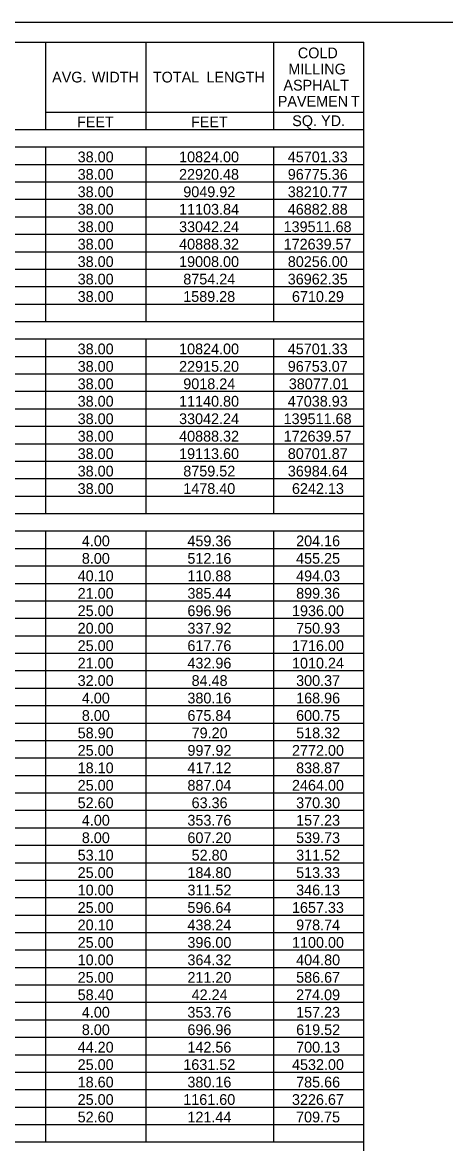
# Model space of a CAD drawing. Extents: x 2261867 to 2275370, y -3124789 to -3122260.
# Drawn here: x 2267667 to 2267860, y -3124304 to -3123790 of the extents above; entities that cross this region are included whole.
import ezdxf

# ---------------------------------------------------------------- set-up
doc = ezdxf.new("R2010")
doc.units = 0
doc.layers.add('Default', color=7, linetype='Continuous')
doc.layers.add('DSN_DRFT_Named-Boundary', color=7, linetype='Continuous')

msp = doc.modelspace()

# ---------------------------------------------------------------- linework, layer by layer
at = {"layer": 'Default'}
for p, q in [((2267341.29, -3123799.38), (2267822.99, -3123799.38)), ((2267677.48, -3123839.36), (2267677.48, -3123799.38)), ((2267723.45, -3123839.36), (2267723.45, -3123799.38)), ((2267781.81, -3123839.36), (2267781.81, -3123799.38)), ((2267822.99, -3124734.8), (2267822.99, -3123799.38)), ((2267822.99, -3124734.8), (2267822.99, -3123799.38)), ((2267677.48, -3123831.36), (2267822.99, -3123831.36)), ((2267677.48, -3123839.36), (2267677.48, -3123831.36)), ((2267723.45, -3123839.36), (2267723.45, -3123831.36)), ((2267341.29, -3123839.36), (2267822.99, -3123839.36)), ((2267341.29, -3123847.35), (2267822.99, -3123847.35)), ((2267341.29, -3123847.35), (2267822.99, -3123847.35)), ((2267677.48, -3123927.3), (2267677.48, -3123847.35)), ((2267677.48, -3123927.3), (2267677.48, -3123847.35)), ((2267723.45, -3123927.3), (2267723.45, -3123847.35)), ((2267781.81, -3123927.3), (2267781.81, -3123847.35)), ((2267341.29, -3123855.35), (2267822.99, -3123855.35)), ((2267723.45, -3123855.35), (2267822.99, -3123855.35)), ((2267382.46, -3123863.34), (2267723.45, -3123863.34)), ((2267677.48, -3123863.34), (2267723.45, -3123863.34)), ((2267723.45, -3123863.34), (2267822.99, -3123863.34)), ((2267723.45, -3123871.34), (2267723.45, -3123863.34)), ((2267382.46, -3123871.34), (2267822.99, -3123871.34)), ((2267677.48, -3123871.34), (2267822.99, -3123871.34)), ((2267382.46, -3123879.33), (2267822.99, -3123879.33)), ((2267677.48, -3123879.33), (2267781.81, -3123879.33)), ((2267781.81, -3123879.33), (2267822.99, -3123879.33)), ((2267382.46, -3123887.33), (2267781.81, -3123887.33)), ((2267677.48, -3123887.33), (2267781.81, -3123887.33)), ((2267781.81, -3123887.33), (2267822.99, -3123887.33)), ((2267781.81, -3123895.32), (2267781.81, -3123887.33)), ((2267341.29, -3123895.32), (2267822.99, -3123895.32)), ((2267723.45, -3123903.32), (2267723.45, -3123895.32)), ((2267781.81, -3123895.32), (2267822.99, -3123895.32)), ((2267382.46, -3123903.32), (2267822.99, -3123903.32)), ((2267677.48, -3123903.32), (2267822.99, -3123903.32)), ((2267382.46, -3123911.31), (2267822.99, -3123911.31)), ((2267677.48, -3123911.31), (2267781.81, -3123911.31)), ((2267781.81, -3123911.31), (2267822.99, -3123911.31)), ((2267382.46, -3123919.31), (2267822.99, -3123919.31)), ((2267677.48, -3123919.31), (2267781.81, -3123919.31)), ((2267781.81, -3123919.31), (2267822.99, -3123919.31)), ((2267341.29, -3123927.3), (2267822.99, -3123927.3)), ((2267423.64, -3123927.3), (2267677.48, -3123927.3)), ((2267677.48, -3123927.3), (2267723.45, -3123927.3)), ((2267723.45, -3123927.3), (2267822.99, -3123927.3)), ((2267341.29, -3123935.3), (2267822.99, -3123935.3)), ((2267677.48, -3124015.25), (2267677.48, -3123935.3)), ((2267677.48, -3124015.25), (2267677.48, -3123935.3)), ((2267723.45, -3124015.25), (2267723.45, -3123935.3)), ((2267723.45, -3123943.29), (2267723.45, -3123935.3)), ((2267781.81, -3124015.25), (2267781.81, -3123935.3)), ((2267781.81, -3123943.29), (2267781.81, -3123935.3)), ((2267341.29, -3123943.29), (2267822.99, -3123943.29)), ((2267723.45, -3123943.29), (2267822.99, -3123943.29)), ((2267341.29, -3123951.29), (2267822.99, -3123951.29)), ((2267723.45, -3123951.29), (2267781.81, -3123951.29)), ((2267781.81, -3123951.29), (2267822.99, -3123951.29)), ((2267382.46, -3123959.28), (2267822.99, -3123959.28)), ((2267677.48, -3123959.28), (2267822.99, -3123959.28)), ((2267723.45, -3123967.28), (2267723.45, -3123959.28)), ((2267382.46, -3123967.28), (2267822.99, -3123967.28)), ((2267677.48, -3123967.28), (2267822.99, -3123967.28)), ((2267382.46, -3123975.27), (2267822.99, -3123975.27)), ((2267677.48, -3123975.27), (2267822.99, -3123975.27)), ((2267382.46, -3123983.27), (2267822.99, -3123983.27)), ((2267677.48, -3123983.27), (2267781.81, -3123983.27)), ((2267781.81, -3123983.27), (2267822.99, -3123983.27)), ((2267382.46, -3123991.26), (2267822.99, -3123991.26)), ((2267677.48, -3123991.26), (2267781.81, -3123991.26)), ((2267781.81, -3123991.26), (2267822.99, -3123991.26)), ((2267382.46, -3123999.26), (2267822.99, -3123999.26)), ((2267677.48, -3123999.26), (2267781.81, -3123999.26)), ((2267781.81, -3123999.26), (2267822.99, -3123999.26)), ((2267382.46, -3124007.25), (2267822.99, -3124007.25)), ((2267677.48, -3124007.25), (2267781.81, -3124007.25)), ((2267781.81, -3124007.25), (2267822.99, -3124007.25)), ((2267341.29, -3124015.25), (2267822.99, -3124015.25)), ((2267423.64, -3124015.25), (2267677.48, -3124015.25)), ((2267677.48, -3124015.25), (2267781.81, -3124015.25)), ((2267781.81, -3124015.25), (2267822.99, -3124015.25)), ((2267341.29, -3124023.24), (2267822.99, -3124023.24)), ((2267677.48, -3124023.24), (2267723.45, -3124023.24)), ((2267677.48, -3124303.07), (2267677.48, -3124023.24)), ((2267677.48, -3124303.07), (2267677.48, -3124023.24)), ((2267723.45, -3124023.24), (2267781.81, -3124023.24)), ((2267723.45, -3124303.07), (2267723.45, -3124023.24)), ((2267723.45, -3124303.07), (2267723.45, -3124023.24)), ((2267781.81, -3124303.07), (2267781.81, -3124023.24)), ((2267781.81, -3124303.07), (2267781.81, -3124023.24)), ((2267341.29, -3124031.24), (2267781.81, -3124031.24)), ((2267723.45, -3124031.24), (2267781.81, -3124031.24)), ((2267781.81, -3124031.24), (2267822.99, -3124031.24)), ((2267341.29, -3124039.23), (2267781.81, -3124039.23)), ((2267723.45, -3124039.23), (2267781.81, -3124039.23)), ((2267781.81, -3124039.23), (2267822.99, -3124039.23)), ((2267341.29, -3124047.23), (2267781.81, -3124047.23)), ((2267723.45, -3124047.23), (2267781.81, -3124047.23)), ((2267781.81, -3124047.23), (2267822.99, -3124047.23)), ((2267341.29, -3124055.22), (2267781.81, -3124055.22)), ((2267723.45, -3124055.22), (2267781.81, -3124055.22)), ((2267781.81, -3124055.22), (2267822.99, -3124055.22)), ((2267341.29, -3124063.22), (2267781.81, -3124063.22)), ((2267723.45, -3124063.22), (2267781.81, -3124063.22)), ((2267781.81, -3124063.22), (2267822.99, -3124063.22)), ((2267341.29, -3124071.21), (2267781.81, -3124071.21)), ((2267723.45, -3124071.21), (2267781.81, -3124071.21)), ((2267781.81, -3124071.21), (2267822.99, -3124071.21)), ((2267341.29, -3124079.21), (2267781.81, -3124079.21)), ((2267723.45, -3124079.21), (2267781.81, -3124079.21)), ((2267781.81, -3124079.21), (2267822.99, -3124079.21)), ((2267341.29, -3124087.2), (2267781.81, -3124087.2)), ((2267723.45, -3124087.2), (2267781.81, -3124087.2)), ((2267781.81, -3124087.2), (2267822.99, -3124087.2)), ((2267341.29, -3124095.2), (2267781.81, -3124095.2)), ((2267723.45, -3124095.2), (2267781.81, -3124095.2)), ((2267781.81, -3124095.2), (2267822.99, -3124095.2)), ((2267341.29, -3124103.19), (2267781.81, -3124103.19)), ((2267723.45, -3124103.19), (2267781.81, -3124103.19)), ((2267781.81, -3124103.19), (2267822.99, -3124103.19)), ((2267341.29, -3124111.19), (2267781.81, -3124111.19)), ((2267723.45, -3124111.19), (2267781.81, -3124111.19)), ((2267781.81, -3124111.19), (2267822.99, -3124111.19)), ((2267341.29, -3124119.18), (2267781.81, -3124119.18)), ((2267723.45, -3124119.18), (2267781.81, -3124119.18)), ((2267781.81, -3124119.18), (2267822.99, -3124119.18)), ((2267341.29, -3124127.18), (2267781.81, -3124127.18)), ((2267723.45, -3124127.18), (2267781.81, -3124127.18)), ((2267781.81, -3124127.18), (2267822.99, -3124127.18)), ((2267341.29, -3124135.17), (2267781.81, -3124135.17)), ((2267723.45, -3124135.17), (2267781.81, -3124135.17)), ((2267781.81, -3124135.17), (2267822.99, -3124135.17)), ((2267341.29, -3124143.17), (2267781.81, -3124143.17)), ((2267723.45, -3124143.17), (2267781.81, -3124143.17)), ((2267781.81, -3124143.17), (2267822.99, -3124143.17)), ((2267341.29, -3124151.16), (2267781.81, -3124151.16)), ((2267723.45, -3124151.16), (2267781.81, -3124151.16)), ((2267781.81, -3124151.16), (2267822.99, -3124151.16)), ((2267341.29, -3124159.16), (2267781.81, -3124159.16)), ((2267723.45, -3124159.16), (2267781.81, -3124159.16)), ((2267781.81, -3124159.16), (2267822.99, -3124159.16)), ((2267341.29, -3124167.15), (2267781.81, -3124167.15)), ((2267723.45, -3124167.15), (2267781.81, -3124167.15)), ((2267781.81, -3124167.15), (2267822.99, -3124167.15)), ((2267341.29, -3124175.15), (2267781.81, -3124175.15)), ((2267723.45, -3124175.15), (2267781.81, -3124175.15)), ((2267781.81, -3124175.15), (2267822.99, -3124175.15)), ((2267341.29, -3124183.14), (2267781.81, -3124183.14)), ((2267723.45, -3124183.14), (2267781.81, -3124183.14)), ((2267781.81, -3124183.14), (2267822.99, -3124183.14)), ((2267341.29, -3124191.14), (2267781.81, -3124191.14)), ((2267723.45, -3124191.14), (2267781.81, -3124191.14)), ((2267781.81, -3124191.14), (2267822.99, -3124191.14)), ((2267341.29, -3124199.13), (2267781.81, -3124199.13)), ((2267723.45, -3124199.13), (2267781.81, -3124199.13)), ((2267781.81, -3124199.13), (2267822.99, -3124199.13)), ((2267341.29, -3124207.13), (2267781.81, -3124207.13)), ((2267723.45, -3124207.13), (2267781.81, -3124207.13)), ((2267781.81, -3124207.13), (2267822.99, -3124207.13)), ((2267341.29, -3124215.12), (2267781.81, -3124215.12)), ((2267723.45, -3124215.12), (2267781.81, -3124215.12)), ((2267781.81, -3124215.12), (2267822.99, -3124215.12)), ((2267341.29, -3124223.12), (2267781.81, -3124223.12)), ((2267723.45, -3124223.12), (2267781.81, -3124223.12)), ((2267781.81, -3124223.12), (2267822.99, -3124223.12)), ((2267341.29, -3124231.11), (2267781.81, -3124231.11)), ((2267723.45, -3124231.11), (2267781.81, -3124231.11)), ((2267781.81, -3124231.11), (2267822.99, -3124231.11)), ((2267341.29, -3124239.11), (2267781.81, -3124239.11)), ((2267723.45, -3124239.11), (2267781.81, -3124239.11)), ((2267781.81, -3124239.11), (2267822.99, -3124239.11)), ((2267341.29, -3124247.1), (2267781.81, -3124247.1)), ((2267723.45, -3124247.1), (2267781.81, -3124247.1)), ((2267781.81, -3124247.1), (2267822.99, -3124247.1)), ((2267341.29, -3124255.1), (2267781.81, -3124255.1)), ((2267723.45, -3124255.1), (2267781.81, -3124255.1)), ((2267781.81, -3124255.1), (2267822.99, -3124255.1)), ((2267341.29, -3124263.09), (2267781.81, -3124263.09)), ((2267677.48, -3124263.09), (2267781.81, -3124263.09)), ((2267781.81, -3124263.09), (2267822.99, -3124263.09)), ((2267341.29, -3124271.09), (2267781.81, -3124271.09)), ((2267677.48, -3124271.09), (2267781.81, -3124271.09)), ((2267781.81, -3124271.09), (2267822.99, -3124271.09)), ((2267341.29, -3124279.08), (2267781.81, -3124279.08)), ((2267677.48, -3124279.08), (2267781.81, -3124279.08)), ((2267781.81, -3124279.08), (2267822.99, -3124279.08)), ((2267341.29, -3124287.08), (2267781.81, -3124287.08)), ((2267677.48, -3124287.08), (2267781.81, -3124287.08)), ((2267781.81, -3124287.08), (2267822.99, -3124287.08)), ((2267341.29, -3124295.07), (2267781.81, -3124295.07)), ((2267677.48, -3124295.07), (2267781.81, -3124295.07)), ((2267781.81, -3124295.07), (2267822.99, -3124295.07)), ((2267341.29, -3124303.07), (2267677.48, -3124303.07)), ((2267341.29, -3124303.07), (2267822.99, -3124303.07)), ((2267677.48, -3124303.07), (2267781.81, -3124303.07)), ((2267781.81, -3124303.07), (2267822.99, -3124303.07))]:
    msp.add_line(p, q, dxfattribs=at)
at = {"layer": 'DSN_DRFT_Named-Boundary'}
msp.add_lwpolyline([(2266769.64, -3124789.38), (2268394.64, -3124789.38), (2268394.64, -3123790.32), (2266769.64, -3123790.32)], close=True, dxfattribs=at)

# ---------------------------------------------------------------- texts
at = {"layer": 'Default'}
for s, p in [('COLD', (2267792.83, -3123806.76)), ('AVG.', (2267680.34, -3123817.83)), (' WIDTH', (2267696.68, -3123817.83)), ('TOTAL', (2267726.46, -3123817.83)), (' LENGTH', (2267749.16, -3123817.83)), ('MILLING', (2267788.48, -3123814.14)), ('ASPHALT', (2267786.24, -3123821.52)), ('PAVEMEN', (2267783.65, -3123828.9)), ('T', (2267817.1, -3123828.9)), ('FEET', (2267691.75, -3123838.37)), ('FEET', (2267743.92, -3123838.37)), ('SQ.', (2267790.27, -3123837.82)), (' YD.', (2267801.64, -3123837.82)), ('38.00', (2267692.03, -3123854.36)), ('10824.00', (2267738.47, -3123854.36)), ('45701.33', (2267788.23, -3123854.36)), ('38.00', (2267692.03, -3123862.36)), ('22920.48', (2267738.45, -3123862.36)), ('96775.36', (2267788.23, -3123862.36)), ('38.00', (2267692.03, -3123870.35)), ('9049.92', (2267740.39, -3123870.35)), ('38210.77', (2267788.23, -3123870.35)), ('38.00', (2267692.03, -3123878.35)), ('11103.84', (2267738.47, -3123878.35)), ('46882.88', (2267788.22, -3123878.35)), ('38.00', (2267692.03, -3123886.34)), ('33042.24', (2267738.47, -3123886.34)), ('139511.68', (2267786.31, -3123886.34)), ('38.00', (2267692.03, -3123894.34)), ('40888.32', (2267738.48, -3123894.34)), ('172639.57', (2267786.32, -3123894.34)), ('38.00', (2267692.03, -3123902.33)), ('19008.00', (2267738.47, -3123902.33)), ('80256.00', (2267788.24, -3123902.33)), ('38.00', (2267692.03, -3123910.33)), ('8754.24', (2267740.38, -3123910.33)), ('36962.35', (2267788.21, -3123910.33)), ('38.00', (2267692.03, -3123918.32)), ('1589.28', (2267740.36, -3123918.32)), ('6710.29', (2267790.13, -3123918.32)), ('38.00', (2267692.03, -3123942.31)), ('10824.00', (2267738.47, -3123942.31)), ('45701.33', (2267788.23, -3123942.31)), ('38.00', (2267692.03, -3123950.3)), ('22915.20', (2267738.47, -3123950.3)), ('96753.07', (2267788.23, -3123950.3)), ('38.00', (2267692.03, -3123958.3)), ('9018.24', (2267740.38, -3123958.3)), ('38077.01', (2267788.7, -3123958.3)), ('38.00', (2267692.03, -3123966.29)), ('11140.80', (2267738.47, -3123966.29)), ('47038.93', (2267788.23, -3123966.29)), ('38.00', (2267692.03, -3123974.29)), ('33042.24', (2267738.47, -3123974.29)), ('139511.68', (2267786.31, -3123974.29)), ('38.00', (2267692.03, -3123982.28)), ('40888.32', (2267738.48, -3123982.28)), ('172639.57', (2267786.32, -3123982.28)), ('38.00', (2267692.03, -3123990.28)), ('19113.60', (2267738.47, -3123990.28)), ('80701.87', (2267788.23, -3123990.28)), ('38.00', (2267692.03, -3123998.27)), ('8759.52', (2267740.39, -3123998.27)), ('36984.64', (2267788.24, -3123998.27)), ('38.00', (2267692.03, -3124006.27)), ('1478.40', (2267740.38, -3124006.27)), ('6242.13', (2267790.14, -3124006.27)), ('4.00', (2267693.94, -3124030.25)), ('459.36', (2267742.28, -3124030.25)), ('204.16', (2267792.05, -3124030.25)), ('8.00', (2267693.94, -3124038.25)), ('512.16', (2267742.28, -3124038.25)), ('455.25', (2267792.03, -3124038.25)), ('40.10', (2267692.03, -3124046.24)), ('110.88', (2267742.27, -3124046.24)), ('494.03', (2267792.05, -3124046.24)), ('21.00', (2267692.03, -3124054.24)), ('385.44', (2267742.29, -3124054.24)), ('899.36', (2267792.05, -3124054.24)), ('25.00', (2267692.03, -3124062.23)), ('696.96', (2267742.28, -3124062.23)), ('1936.00', (2267790.15, -3124062.23)), ('20.00', (2267692.03, -3124070.23)), ('337.92', (2267742.3, -3124070.23)), ('750.93', (2267792.05, -3124070.23)), ('25.00', (2267692.03, -3124078.22)), ('617.76', (2267742.28, -3124078.22)), ('1716.00', (2267790.15, -3124078.22)), ('21.00', (2267692.03, -3124086.22)), ('432.96', (2267742.28, -3124086.22)), ('1010.24', (2267790.15, -3124086.22)), ('32.00', (2267692.03, -3124094.21)), ('84.48', (2267744.19, -3124094.21)), ('300.37', (2267792.05, -3124094.21)), ('4.00', (2267693.94, -3124102.21)), ('380.16', (2267742.28, -3124102.21)), ('168.96', (2267792.05, -3124102.21)), ('8.00', (2267693.94, -3124110.2)), ('675.84', (2267742.29, -3124110.2)), ('600.75', (2267792.03, -3124110.2)), ('58.90', (2267692.03, -3124118.2)), ('79.20', (2267744.2, -3124118.2)), ('518.32', (2267792.07, -3124118.2)), ('25.00', (2267692.03, -3124126.19)), ('997.92', (2267742.3, -3124126.19)), ('2772.00', (2267790.15, -3124126.19)), ('18.10', (2267692.03, -3124134.19)), ('417.12', (2267742.3, -3124134.19)), ('838.87', (2267792.05, -3124134.19)), ('25.00', (2267692.03, -3124142.18)), ('887.04', (2267742.29, -3124142.18)), ('2464.00', (2267790.15, -3124142.18)), ('52.60', (2267692.03, -3124150.18)), ('63.36', (2267744.19, -3124150.18)), ('370.30', (2267792.06, -3124150.18)), ('4.00', (2267693.94, -3124158.17)), ('353.76', (2267742.28, -3124158.17)), ('157.23', (2267792.05, -3124158.17)), ('8.00', (2267693.94, -3124166.17)), ('607.20', (2267742.29, -3124166.17)), ('539.73', (2267792.05, -3124166.17)), ('53.10', (2267692.03, -3124174.16)), ('52.80', (2267744.2, -3124174.16)), ('311.52', (2267792.07, -3124174.16)), ('25.00', (2267692.03, -3124182.16)), ('184.80', (2267742.29, -3124182.16)), ('513.33', (2267792.05, -3124182.16)), ('10.00', (2267692.03, -3124190.15)), ('311.52', (2267742.3, -3124190.15)), ('346.13', (2267792.05, -3124190.15)), ('25.00', (2267692.03, -3124198.15)), ('596.64', (2267742.29, -3124198.15)), ('1657.33', (2267790.14, -3124198.15)), ('20.10', (2267692.03, -3124206.14)), ('438.24', (2267742.29, -3124206.14)), ('978.74', (2267792.06, -3124206.14)), ('25.00', (2267692.03, -3124214.14)), ('396.00', (2267742.29, -3124214.14)), ('1100.00', (2267790.15, -3124214.14)), ('10.00', (2267692.03, -3124222.13)), ('364.32', (2267742.3, -3124222.13)), ('404.80', (2267792.06, -3124222.13)), ('25.00', (2267692.03, -3124230.13)), ('211.20', (2267742.29, -3124230.13)), ('586.67', (2267792.05, -3124230.13)), ('58.40', (2267692.03, -3124238.12)), ('42.24', (2267744.2, -3124238.12)), ('274.09', (2267792.04, -3124238.12)), ('4.00', (2267693.94, -3124246.12)), ('353.76', (2267742.28, -3124246.12)), ('157.23', (2267792.05, -3124246.12)), ('8.00', (2267693.94, -3124254.11)), ('696.96', (2267742.28, -3124254.11)), ('619.52', (2267792.07, -3124254.11)), ('44.20', (2267692.03, -3124262.11)), ('142.56', (2267742.28, -3124262.11)), ('700.13', (2267792.05, -3124262.11)), ('25.00', (2267692.03, -3124270.1)), ('1631.52', (2267740.39, -3124270.1)), ('4532.00', (2267790.15, -3124270.1)), ('18.60', (2267692.03, -3124278.1)), ('380.16', (2267742.28, -3124278.1)), ('785.66', (2267792.05, -3124278.1)), ('25.00', (2267692.03, -3124286.09)), ('1161.60', (2267740.38, -3124286.09)), ('3226.67', (2267790.14, -3124286.09)), ('52.60', (2267692.03, -3124294.09)), ('121.44', (2267742.29, -3124294.09)), ('709.75', (2267792.03, -3124294.09))]:
    msp.add_text(s, height=4.92, dxfattribs=at).set_placement(p)

doc.saveas('drawing.dxf')
